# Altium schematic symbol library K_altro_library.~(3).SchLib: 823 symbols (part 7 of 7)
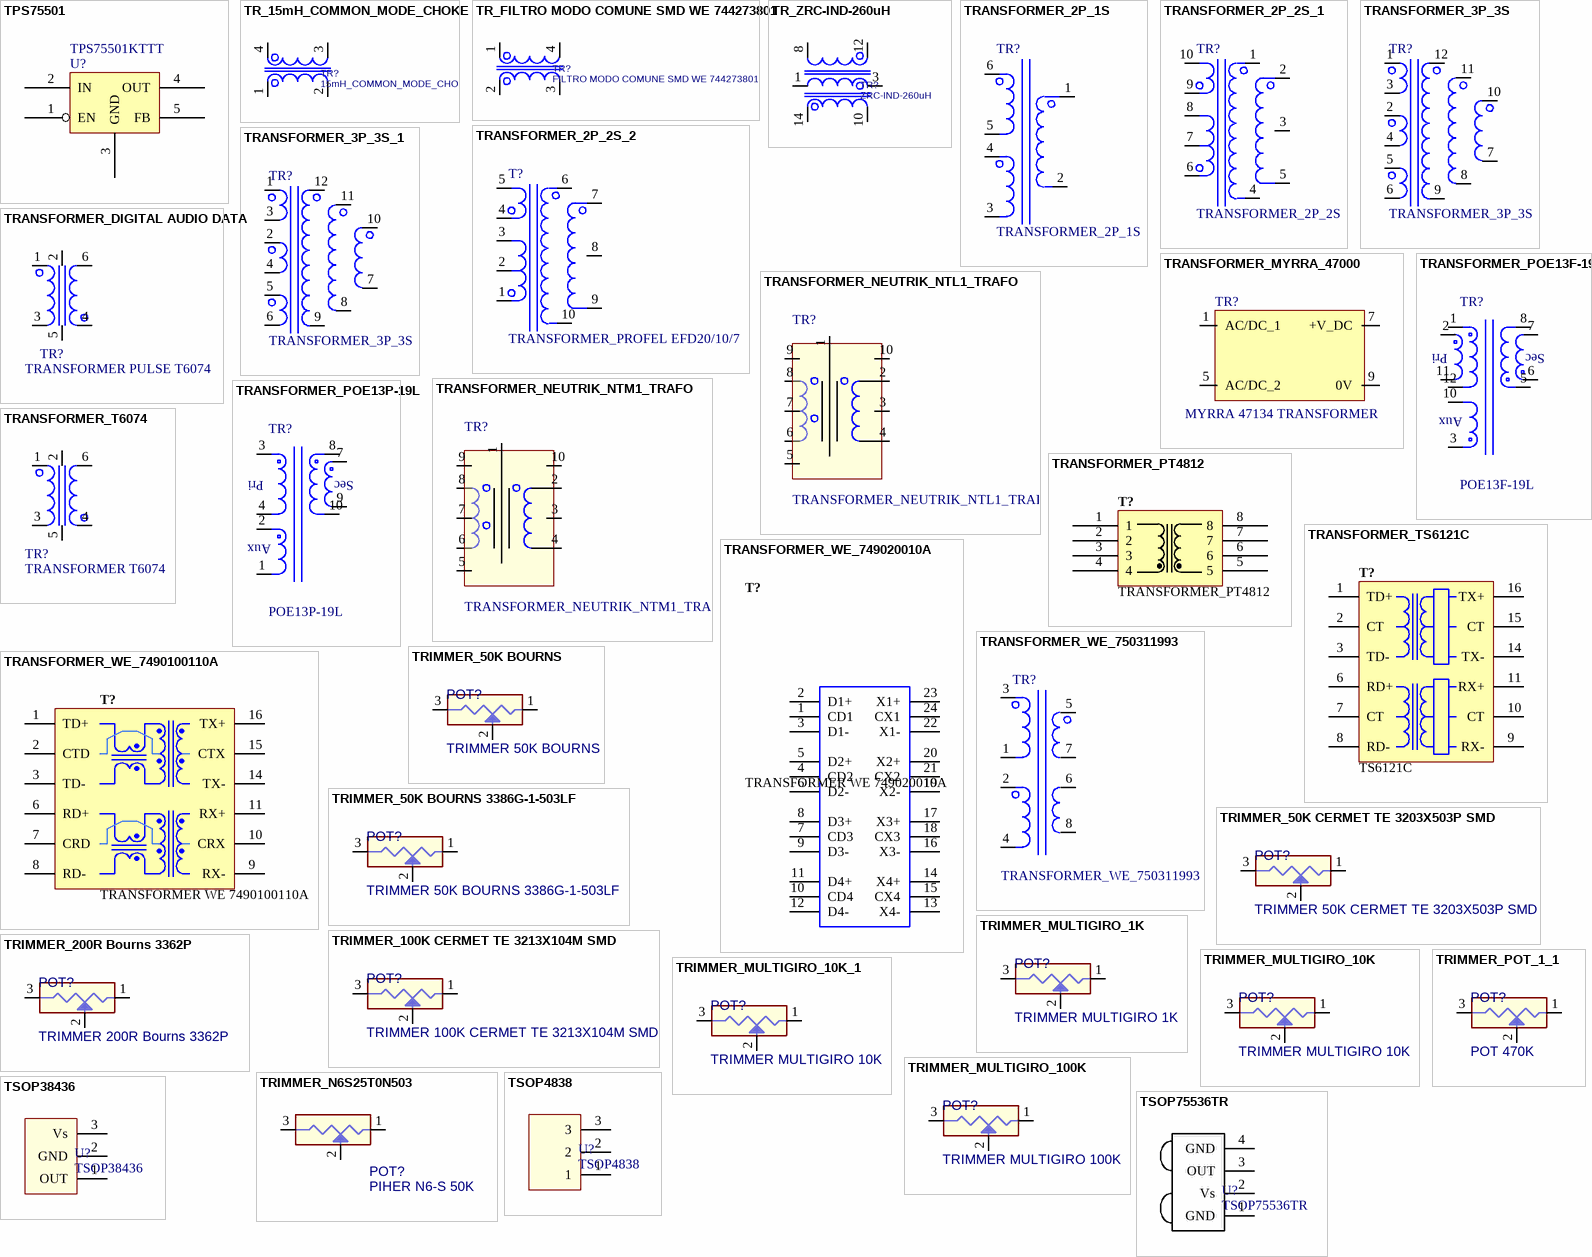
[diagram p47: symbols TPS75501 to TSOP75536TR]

## TRIMMER_50K CERMET TE 3203X503P SMD
designator POT?, comment TRIMMER 50K CERMET TE 3203X503P SMD
Detail: (RS per >10pz); Costo: 0,85; Aggiornato: NO; ContoLavoro: 0
footprint TRIMMER_CERMET 3203 SERIE
pins: 1 A, 2 B, 3 C

## TRIMMER_100K CERMET TE 3213X104M SMD
designator POT?, comment TRIMMER 100K CERMET TE 3213X104M SMD
Detail: (RS per >5pz); Costo: 0,98; Aggiornato: NO; ContoLavoro: 0
footprint TRIMMER_ALPS_RH03A3A
pins: 1 A, 2 B, 3 C

## TRIMMER_200R Bourns 3362P
designator POT?, comment TRIMMER 200R Bourns 3362P
Detail: (RS per >10pz); Value: 200; Costo: 0,70; Aggiornato: NO; ContoLavoro: 0
footprint TRIMMER_Bourns_3362P (Footprint not found)
pins: 1 A, 2 B, 3 C

## TRIMMER_MULTIGIRO_1K
designator POT?, comment TRIMMER MULTIGIRO 1K
Aggiornato: NO; ContoLavoro: 0
footprint TRIMMER_T93YB (Footprint not found)
pins: 1 A, 2 B, 3 C

## TRIMMER_MULTIGIRO_10K
designator POT?, comment TRIMMER MULTIGIRO 10K
Detail: (RS per >5pz); Costo: 1,248; Aggiornato: NO; ContoLavoro: 0
footprint TRIMMER_T93YB (Footprint not found)
pins: 1 A, 2 B, 3 C

## TRIMMER_MULTIGIRO_10K_1
designator POT?, comment TRIMMER MULTIGIRO 10K
TRIMMER MULTIGIRO 10K pin in linea; Detail: (RS per >5pz); Costo: 1,248; Aggiornato: NO; ContoLavoro: 0
footprint TRIMMER_3296W (TRIMMER 3296W)
pins: 1 A, 2 B, 3 C

## TRIMMER_MULTIGIRO_100K
designator POT?, comment TRIMMER MULTIGIRO 100K
Detail: (RS per >50pz); Costo: 1,45; Aggiornato: NO; ContoLavoro: 0
footprint TRIMMER_3296W (TRIMMER 3296W)
pins: 1 A, 2 B, 3 C

## TRIMMER_N6S25T0N503
designator POT?, comment PIHER N6-S 50K
PIHER N6S25T0N-503 TRIMMER 50K; Costo: 0; Aggiornato: NO
footprint TRIMMER PIHER N6S
pins: 1 A, 2 B, 3 C

## TRIMMER_POT_1_1
designator POT?, comment POT 470K
TRIMMER 470K BOURS ALT:RS473-574; Costo: 0; Aggiornato: NO
footprint TRIMMER ORIZ
pins: 1 A, 2 B, 3 C

## TSOP4838
designator U?
Ricevitore IR TSOP4838; Aggiornato: no; Costo: 0,66; Detail: controllare footprint e 3d; ContoLavoro: 0
footprint TSOP4838
pins: 1, 2, 3

## TSOP38436
designator U?
Ricevitore IR TSOP38436; Aggiornato: no; Costo: 0,338; Detail: € RS Pz>50; ContoLavoro: 0
footprint TSOP38436 (Footprint not found)
footprint TSOP38436_SMD_FLAT_MOUNT
footprint TSOP38436_SMD_FLAT_MOUNT_ALT
pins: 1 OUT, 2 GND, 3 Vs

## TSOP75536TR
designator U?
Ricevitore IR TSOP75536TR; Aggiornato: no; Costo: 0,43; Detail: € RS pz>20; ContoLavoro: 0
footprint TSOP75536TR (Footprint not found)
pins: 1 GND, 2 Vs, 3 OUT, 4 GND

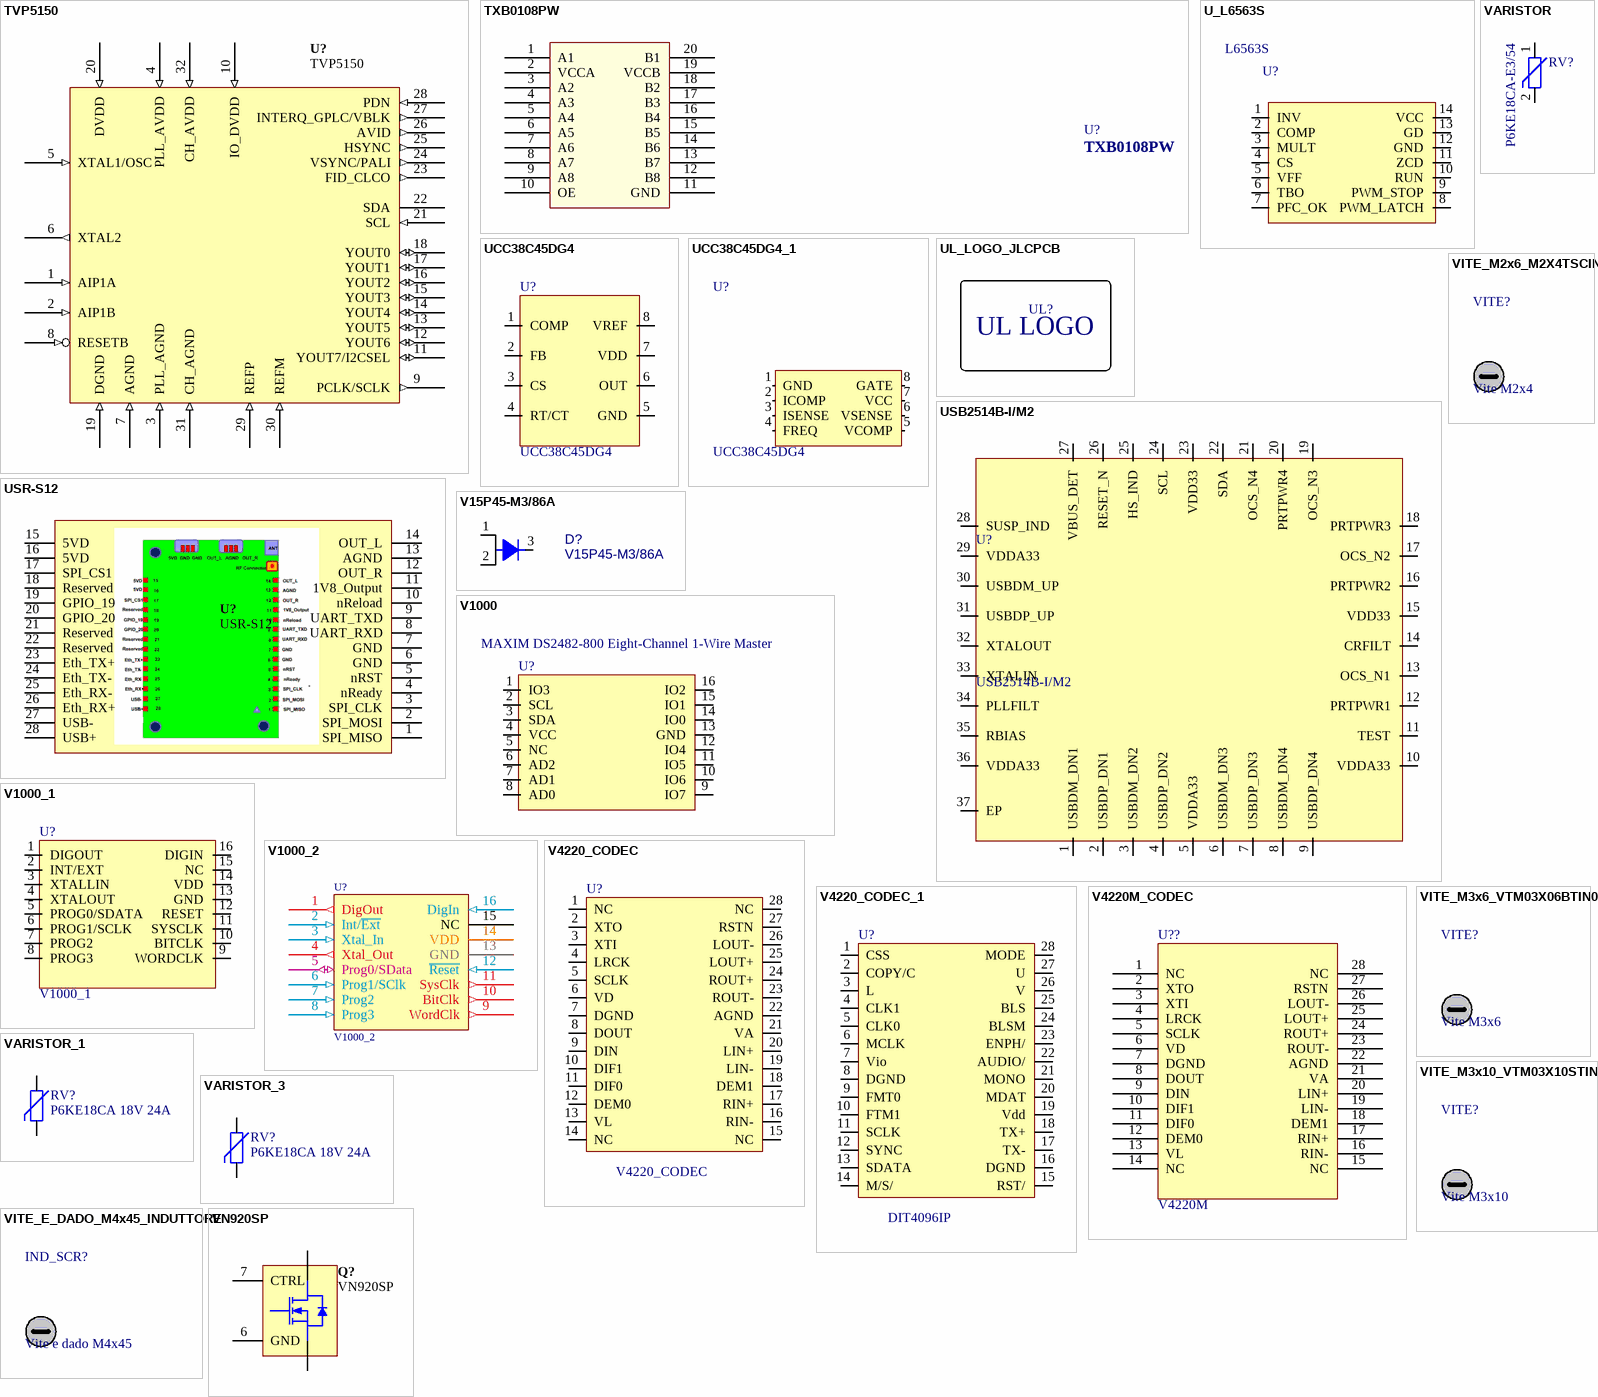
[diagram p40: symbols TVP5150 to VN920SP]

## TVP5150
designator U?
TVP5150AM1PBS, Ultralow Power NTSC/PAL/SECAM Video Decoder With Robust Sync Detector; Aggiornato: NO; Costo: 0
footprint TSQFP50P700X700-32
pins: 1 AIP1A (in), 2 AIP1B (in), 3 PLL_AGND (in), 4 PLL_AVDD (in), 5 XTAL1/OSC (in), 6 XTAL2 (out), 7 AGND (in), 8 RESETB (in), 9 PCLK/SCLK (out), 10 IO_DVDD (in), 11 YOUT7/I2CSEL (io), 12 YOUT6 (io), 13 YOUT5 (io), 14 YOUT4 (io), 15 YOUT3 (io), 16 YOUT2 (io), 17 YOUT1 (io), 18 YOUT0 (io), 19 DGND (in), 20 DVDD (in), 21 SCL (in), 22 SDA (oc), 23 FID_CLCO (out), 24 VSYNC/PALI (out), 25 HSYNC (out), 26 AVID (out), 27 INTERQ_GPLC/VBLK (out), 28 PDN (in), 29 REFP (in), 30 REFM (in), 31 CH_AGND (in), 32 CH_AVDD (in)

## TXB0108PW
designator U?
Detail: 1,12€ RS pz>100; Costo: 1,12; Aggiornato: NO; ContoLavoro: 0
footprint TSSOP20
pins: 1 A1, 2 VCCA, 3 A2, 4 A3, 5 A4, 6 A5, 7 A6, 8 A7, 9 A8, 10 OE, 11 GND, 12 B8, 13 B7, 14 B6, 15 B5, 16 B4, 17 B3, 18 B2, 19 VCCB, 20 B1
2 alternate drawings of the same symbol

## U_L6563S
designator U?, comment L6563S
L6563S TRANSITION-MODE PFC CONTROLLER ST; Costo: 0; Aggiornato: NO
footprint SO14
pins: 1 INV, 2 COMP, 3 MULT, 4 CS, 5 VFF, 6 TBO, 7 PFC_OK, 8 PWM_LATCH, 9 PWM_STOP, 10 RUN, 11 ZCD, 12 GND, 13 GD, 14 VCC

## UCC38C45DG4
designator U?
Costo: 1,534; Aggiornato: NO; ContoLavoro: 0
footprint SO8
pins: 1 COMP, 2 FB, 3 CS, 4 RT/CT, 5 GND, 6 OUT, 7 VDD, 8 VREF

## UCC38C45DG4_1
designator U?, comment UCC38C45DG4
Costo: 1,534; Aggiornato: NO; ContoLavoro: 0
footprint SO8
pins: 1 GND, 2 ICOMP, 3 ISENSE, 4 FREQ, 5 VCOMP, 6 VSENSE, 7 VCC, 8 GATE

## UL_LOGO_JLCPCB
designator UL?  (value not drawn)
footprint UL_JLCPCB_Multilayer_5mmx2mm (UL_LOGO_JLCPCB_Multilayer)
footprint UL_JLCPCB_Multilayer_10mmx5mm (UL_LOGO_JLCPCB_Multilayer)
footprint UL_JLCPCB_Multilayer_15mmx7mm (UL_LOGO_JLCPCB_Multilayer)
footprint UL_JLCPCB_Multilayer_20mmx10mm (UL_LOGO_JLCPCB_Multilayer)
footprint UL_JLCPCB_Multilayer_25mmx12mm (UL_LOGO_JLCPCB_Multilayer)

## USB2514B-I/M2
designator U?
USB 2.0 Hi-Speed Hub Controlle; Costo: 0,4; Aggiornato: s; ContoLavoro: 0
footprint SQFN36_EP (Footprint not found)
footprint SQFN36_EP_VIAS
pins: 1 USBDM_DN1, 2 USBDP_DN1, 3 USBDM_DN2, 4 USBDP_DN2, 5 VDDA33, 6 USBDM_DN3, 7 USBDP_DN3, 8 USBDM_DN4, 9 USBDP_DN4, 10 VDDA33, 11 TEST, 12 PRTPWR1, 13 OCS_N1, 14 CRFILT, 15 VDD33, 16 PRTPWR2, 17 OCS_N2, 18 PRTPWR3, 19 OCS_N3, 20 PRTPWR4, 21 OCS_N4, 22 SDA, 23 VDD33, 24 SCL, 25 HS_IND, 26 RESET_N, 27 VBUS_DET, 28 SUSP_IND, 29 VDDA33, 30 USBDM_UP, 31 USBDP_UP, 32 XTALOUT, 33 XTALIN, 34 PLLFILT, 35 RBIAS, 36 VDDA33, 37 EP

## USR-S12
designator U?
USR-S12 WI-FI Audio Module; Aggiornato: NO; Costo: 0
pins: 1 SPI_MISO, 2 SPI_MOSI, 3 SPI_CLK, 4 nReady, 5 nRST, 6 GND, 7 GND, 8 UART_RXD, 9 UART_TXD, 10 nReload, 11 1V8_Output, 12 OUT_R, 13 AGND, 14 OUT_L, 15 5VD, 16 5VD, 17 SPI_CS1, 18 Reserved, 19 GPIO_19, 20 GPIO_20, 21 Reserved, 22 Reserved, 23 Eth_TX+, 24 Eth_TX-, 25 Eth_RX-, 26 Eth_RX+, 27 USB-, 28 USB+

## V15P45-M3/86A
designator D?
V15P45-M3/86A Diodo e raddrizzatore Schottky 15 Amp 45 Volt; Detail: € pz. 1.00; Aggiornato: S; Costo: 0,772; ContoLavoro: 0
footprint V15P45-M3/86A
pins: 1, 2, 3

## V1000
designator U?, comment MAXIM DS2482-800 Eight-Channel 1-Wire Master
Aggiornato: NO; Costo: 0
footprint SO16
pins: 1 IO3, 2 SCL, 3 SDA, 4 VCC, 5 NC, 6 AD2, 7 AD1, 8 AD0, 9 IO7, 10 IO6, 11 IO5, 12 IO4, 13 GND, 14 IO0, 15 IO1, 16 IO2

## V1000_1
designator U?
Aggiornato: NO; Costo: 0
footprint SOIC127P1030-16N (SOIC, 16-Leads, Body 10.3x7.5mm, Pitch 1.27mm, IPC Medium Density)
pins: 1 DIGOUT, 2 INT/EXT, 3 XTALLIN, 4 XTALOUT, 5 PROG0/SDATA, 6 PROG1/SCLK, 7 PROG2, 8 PROG3, 9 WORDCLK, 10 BITCLK, 11 SYSCLK, 12 RESET, 13 GND, 14 VDD, 15 NC, 16 DIGIN

## V1000_2
designator U?
Low-Cost One-Chip Multi-Effects DSP; Part Field 1: COOLAUDIO V1000; Aggiornato: NO; Costo: 0
footprint SOIC300-16N (SOIC, 16-Leads, Body 10.3x7.5mm, Pitch 1.27mm, IPC Medium Density)
pins: 1 DigOut (out), 2 Int/~{Ext} (in), 3 Xtal_In (in), 4 Xtal_Out (out), 5 Prog0/SData (io), 6 Prog1/SClk (in), 7 Prog2 (in), 8 Prog3 (in), 9 WordClk (out), 10 BitClk (out), 11 SysClk (out), 12 ~{Reset} (in), 13 GND (power), 14 VDD (power), 15 NC, 16 DigIn (in)

## V4220_CODEC
designator U?
Aggiornato: NO; Costo: 0
footprint SSOP-28 (SOP, 28-Leads, Body 10,5x5,6mm (max), Pitch 0,65mm, IPC Medium Density)
pins: 1 NC, 2 XTO, 3 XTI, 4 LRCK, 5 SCLK, 6 VD, 7 DGND, 8 DOUT, 9 DIN, 10 DIF1, 11 DIF0, 12 DEM0, 13 VL, 14 NC, 15 NC, 16 RIN-, 17 RIN+, 18 DEM1, 19 LIN-, 20 LIN+, 21 VA, 22 AGND, 23 ROUT-, 24 ROUT+, 25 LOUT+, 26 LOUT-, 27 RSTN, 28 NC

## V4220_CODEC_1
designator U?, comment DIT4096IP
Aggiornato: NO; Costo: 0
footprint SSOP-28 (SOP, 28-Leads, Body 10,5x5,6mm (max), Pitch 0,65mm, IPC Medium Density)
pins: 1 CSS, 2 COPY/C, 3 L, 4 CLK1, 5 CLK0, 6 MCLK, 7 Vio, 8 DGND, 9 FMT0, 10 FTM1, 11 SCLK, 12 SYNC, 13 SDATA, 14 M/S/, 15 RST/, 16 DGND, 17 TX-, 18 TX+, 19 Vdd, 20 MDAT, 21 MONO, 22 AUDIO/, 23 ENPH/, 24 BLSM, 25 BLS, 26 V, 27 U, 28 MODE

## V4220M_CODEC
designator U??, comment V4220M
24-Bit Stereo Codec with 110dB SNR; Aggiornato: NO; Costo: 0
footprint SSOP-28 (SOP, 28-Leads, Body 10,5x5,6mm (max), Pitch 0,65mm, IPC Medium Density)
pins: 1 NC, 2 XTO, 3 XTI, 4 LRCK, 5 SCLK, 6 VD, 7 DGND, 8 DOUT, 9 DIN, 10 DIF1, 11 DIF0, 12 DEM0, 13 VL, 14 NC, 15 NC, 16 RIN-, 17 RIN+, 18 DEM1, 19 LIN-, 20 LIN+, 21 VA, 22 AGND, 23 ROUT-, 24 ROUT+, 25 LOUT+, 26 LOUT-, 27 RSTN, 28 NC

## VARISTOR
designator RV?, comment P6KE18CA-E3/54
VARISTORE VISHAY P6KE18CA-E3/54 ALT:RS 699-7972; Costo: 0,155; Aggiornato: NO; ContoLavoro: 0
footprint DO15
pins: 1, 2

## VARISTOR_1
designator RV?, comment P6KE18CA 18V 24A
P6KE18CA 18V 24A MOD. ST REEL(1000); Costo: 0; Aggiornato: NO
footprint VAR-W3.18-L20.83-P7.62X2.54/10.16X2.54-DR1.25
footprint DO15
footprint DO214AA_1
pins: 1, 2

## VARISTOR_3
designator RV?, comment P6KE18CA 18V 24A
Costo: 0; Aggiornato: NO
footprint VAR-W3.18-L20.83-P7.62X2.54/10.16X2.54-DR1.25
footprint P6KE-LF_1
footprint DO214AA_1
pins: 1, 2

## VITE_E_DADO_M4x45_INDUTTORE
designator IND_SCR?, comment Vite e dado M4x45  (mechanical)
Costo: 0; Aggiornato: NO
pins: 1 hidden
1 alternate drawing of the same symbol

## VITE_M2x6_M2X4TSCIN
designator VITE?, comment Vite M2x4  (mechanical)
Costo: 0,0070; Hpcode: M2X4TSCIN; Aggiornato: s; ContoLavoro: 1
pins: 1 hidden
1 alternate drawing of the same symbol

## VITE_M3x6_VTM03X06BTIN0
designator VITE?, comment Vite M3x6  (mechanical)
Costo: 0,0070; Hpcode: VTM03X06BTIN0; Aggiornato: s; ContoLavoro: 1
pins: 1 hidden
1 alternate drawing of the same symbol

## VITE_M3x10_VTM03X10STINO
designator VITE?, comment Vite M3x10  (mechanical)
Costo: 0,02; Hpcode: VTM03X10STINO; Aggiornato: s; ContoLavoro: 1
pins: 1 hidden
1 alternate drawing of the same symbol

## VN920SP
designator Q?
Single Channel High Side SSR; Rated Voltage: mV; Switch Type: SPDT; Aggiornato: NO; Costo: 0
footprint PowerSO-10_M
pins: 1 OUTPUT, 2 OUTPUT, 4 OUTPUT, 5 OUTPUT, 6 GND, 7 CTRL, 11 VCC

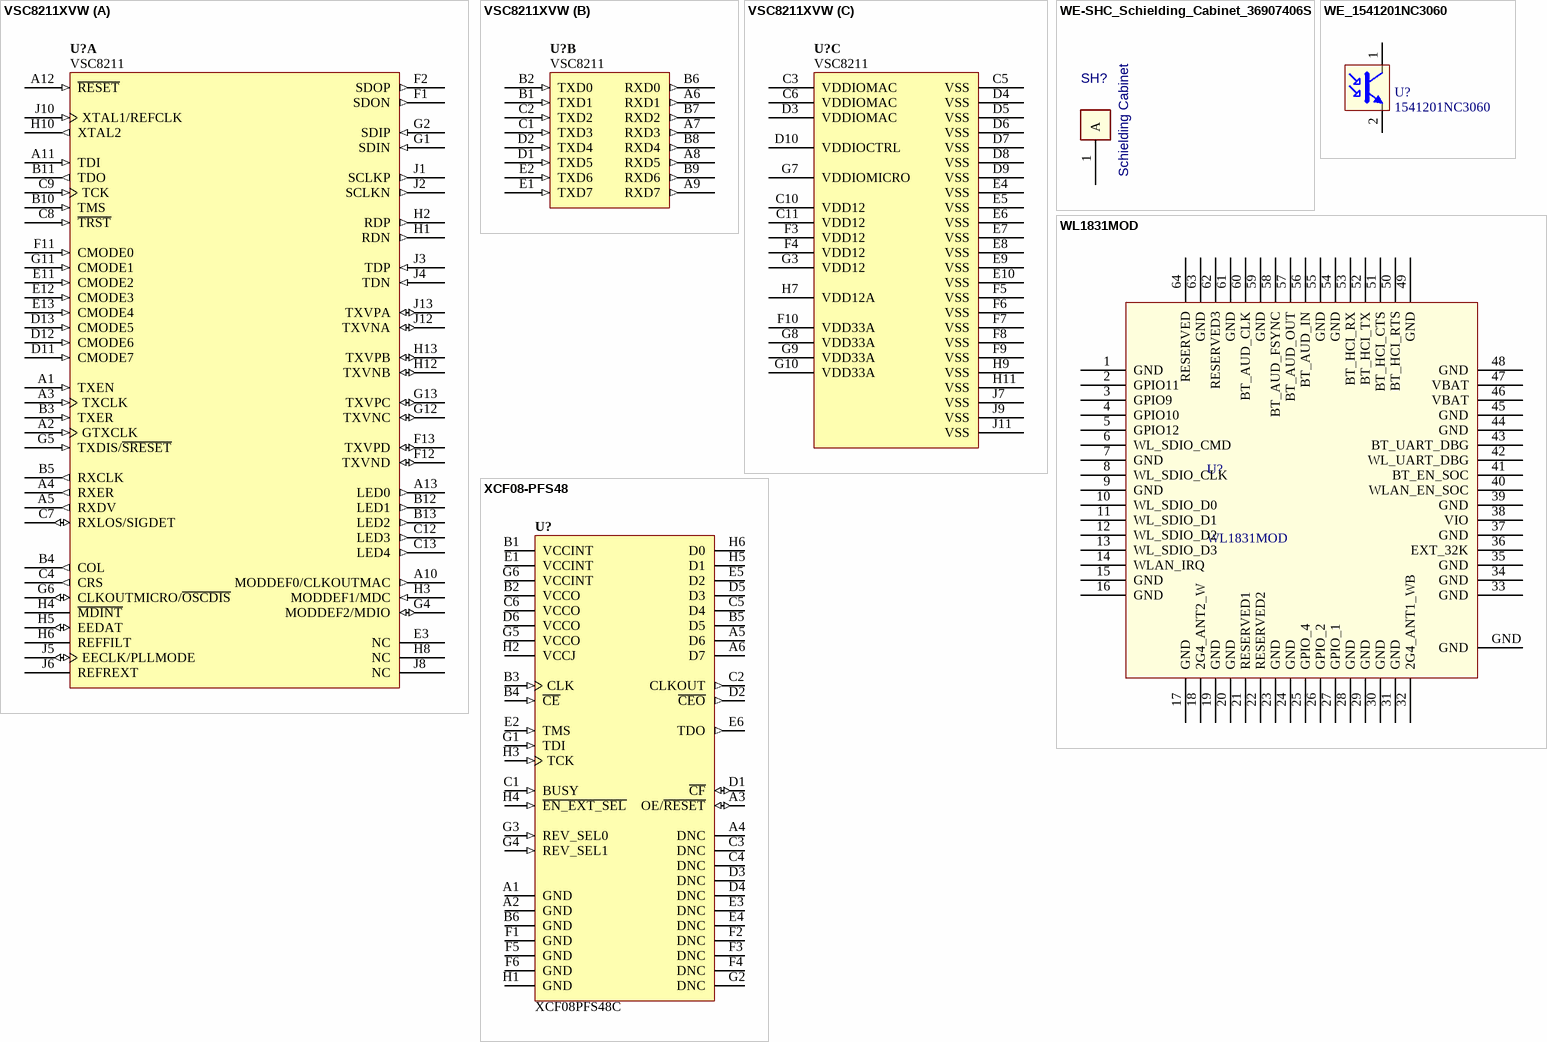
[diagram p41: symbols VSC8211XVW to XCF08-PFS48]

## VSC8211XVW
designator U?, comment VSC8211
Ethernet PHY, Gigabit, Vitesse, VSC8211; Aggiornato: NO; Costo: 0
footprint BGA117C100P9X13_1000X1400X170
part A pins: A1 TXEN (in), A2 GTXCLK (in), A3 TXCLK (in), A4 RXER (out), A5 RXDV (out), A10 MODDEF0/CLKOUTMAC (out), A11 TDI (in), A12 ~{RESET} (in), A13 LED0 (out), B3 TXER (in), B4 COL (out), B5 RXCLK (out), B10 TMS (in), B11 TDO (out), B12 LED1 (out), B13 LED2 (out), C4 CRS (out), C7 RXLOS/SIGDET (io), C8 ~{TRST} (in), C9 TCK (in), C12 LED3 (out), C13 LED4 (out), D11 CMODE7 (in), D12 CMODE6 (in), D13 CMODE5 (in), E3 NC, E11 CMODE2 (in), E12 CMODE3 (in), E13 CMODE4 (in), F1 SDON (out), F2 SDOP (out), F11 CMODE0 (in), F12 TXVND (io), F13 TXVPD (io), G1 SDIN (in), G2 SDIP (in), G4 MODDEF2/MDIO (io), G5 TXDIS/~{SRESET} (in), G6 CLKOUTMICRO/~{OSCDIS} (io), G11 CMODE1 (in), G12 TXVNC (io), G13 TXVPC (io), H1 RDN (out), H2 RDP (out), H3 MODDEF1/MDC (in), H4 ~{MDINT} (oc), H5 EEDAT (io), H6 REFFILT, H8 NC, H10 XTAL2 (out), H12 TXVNB (io), H13 TXVPB (io), J1 SCLKP (out), J2 SCLKN (out), J3 TDP (in), J4 TDN (in), J5 EECLK/PLLMODE (io), J6 REFREXT, J8 NC, J10 XTAL1/REFCLK (in), J12 TXVNA (io), J13 TXVPA (io)
part B pins: A6 RXD1 (out), A7 RXD3 (out), A8 RXD5 (out), A9 RXD7 (out), B1 TXD1 (in), B2 TXD0 (in), B6 RXD0 (out), B7 RXD2 (out), B8 RXD4 (out), B9 RXD6 (out), C1 TXD3 (in), C2 TXD2 (in), D1 TXD5 (in), D2 TXD4 (in), E1 TXD7 (in), E2 TXD6 (in)
part C pins: C3 VDDIOMAC (power), C5 VSS (power), C6 VDDIOMAC (power), C10 VDD12 (power), C11 VDD12 (power), D3 VDDIOMAC (power), D4 VSS (power), D5 VSS (power), D6 VSS (power), D7 VSS (power), D8 VSS (power), D9 VSS (power), D10 VDDIOCTRL (power), E4 VSS (power), E5 VSS (power), E6 VSS (power), E7 VSS (power), E8 VSS (power), E9 VSS (power), E10 VSS (power), F3 VDD12 (power), F4 VDD12 (power), F5 VSS (power), F6 VSS (power), F7 VSS (power), F8 VSS (power), F9 VSS (power), F10 VDD33A (power), G3 VDD12 (power), G7 VDDIOMICRO (power), G8 VDD33A (power), G9 VDD33A (power), G10 VDD33A (power), H7 VDD12A (power), H9 VSS (power), H11 VSS (power), J7 VSS (power), J9 VSS (power), J11 VSS (power)

## WE-SHC_Schielding_Cabinet_36907406S
designator SH?, comment Schielding Cabinet
Detail: 0,85€ pz Offerta A19IT015981; Aggiornato: S; Costo: 0,85; ContoLavoro: 0
footprint WE_36907406S (WurthElektronik 36907406S WE-SHC Shielding Cabinet)
pins: 1 A

## WE_1541201NC3060
designator U?, comment 1541201NC3060
IR Phototransistor WE 1541201NC3060; Aggiornato: no; Costo: 0
footprint 1206_REVERSE_IRLED_WE_1541201NC3060
pins: 1 c, 2 e

## WL1831MOD
designator U?
Costo: 16,5; Aggiornato: NO; Detail: 16,5€ Farnell Pz>100; ContoLavoro: 0
footprint WL18XX_E-13.4X13.3-N100_0.75
pins: 1 GND, 2 GPIO11, 3 GPIO9, 4 GPIO10, 5 GPIO12, 6 WL_SDIO_CMD, 7 GND, 8 WL_SDIO_CLK, 9 GND, 10 WL_SDIO_D0, 11 WL_SDIO_D1, 12 WL_SDIO_D2, 13 WL_SDIO_D3, 14 WLAN_IRQ, 15 GND, 16 GND, 17 GND, 18 2G4_ANT2_W, 19 GND, 20 GND, 21 RESERVED1, 22 RESERVED2, 23 GND, 24 GND, 25 GPIO_4, 26 GPIO_2, 27 GPIO_1, 28 GND, 29 GND, 30 GND, 31 GND, 32 2G4_ANT1_WB, 33 GND, 34 GND, 35 GND, 36 EXT_32K, 37 GND, 38 VIO, 39 GND, 40 WLAN_EN_SOC, 41 BT_EN_SOC, 42 WL_UART_DBG, 43 BT_UART_DBG, 44 GND, 45 GND, 46 VBAT, 47 VBAT, 48 GND, 49 GND, 50 BT_HCI_RTS, 51 BT_HCI_CTS, 52 BT_HCI_TX, 53 BT_HCI_RX, 54 GND, 55 GND, 56 BT_AUD_IN, 57 BT_AUD_OUT, 58 BT_AUD_FSYNC, 59 GND, 60 BT_AUD_CLK, 61 GND, 62 RESERVED3, 63 GND, 64 RESERVED, GND

## XCF08-PFS48
designator U?, comment XCF08PFS48C
XCF00P Series, Platform Flash In-System Programmable Configuration 1.8V PROM, 48 Ball BGA, 8-Megabit, Commercial Grade; Aggiornato: NO; Costo: 0
footprint BGA80P8X6-48
pins: A1 GND (power), A2 GND (power), A3 OE/~{RESET} (io), A4 DNC, A5 D6 (hiz), A6 D7 (hiz), B1 VCCINT (power), B2 VCCO (power), B3 CLK (in), B4 ~{CE} (in), B5 D5 (hiz), B6 GND (power), C1 BUSY (in), C2 CLKOUT (out), C3 DNC, C4 DNC, C5 D4 (hiz), C6 VCCO (power), D1 ~{CF} (io), D2 ~{CEO} (out), D3 DNC, D4 DNC, D5 D3 (hiz), D6 VCCO (power), E1 VCCINT (power), E2 TMS (in), E3 DNC, E4 DNC, E5 D2 (hiz), E6 TDO (out), F1 GND (power), F2 DNC, F3 DNC, F4 DNC, F5 GND (power), F6 GND (power), G1 TDI (in), G2 DNC, G3 REV_SEL0 (in), G4 REV_SEL1 (in), G5 VCCO (power), G6 VCCINT (power), H1 GND (power), H2 VCCJ (power), H3 TCK (in), H4 ~{EN_EXT_SEL} (in), H5 D1 (hiz), H6 D0 (hiz)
